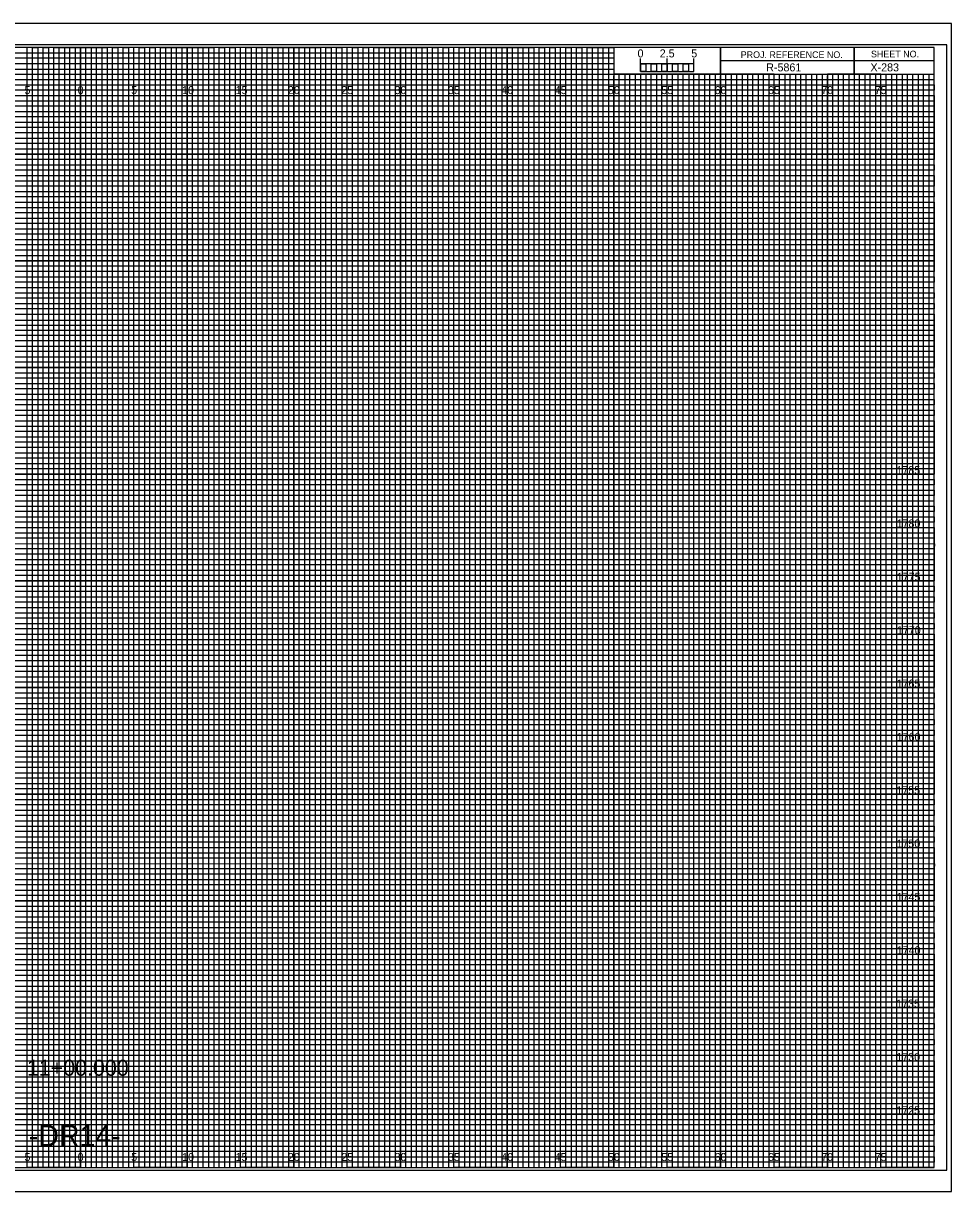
# Model space of a CAD drawing. Extents: x -7 to 162, y -2 to 437.
# Drawn here: x 74.6 to 161.7, y 107.7 to 217.2 of the extents above; entities that cross this region are included whole.
import ezdxf

# ---------------------------------------------------------------- set-up
doc = ezdxf.new("R2010")
doc.units = 0
for name, color, linetype in [('Prop Horizontal Alignment', 7, 'Continuous'), ('Prop XS Alignment Label', 7, 'Continuous'), ('Prop XS Bar Scale Labels', 7, 'Continuous'), ('Prop XS Project Number', 7, 'Continuous'), ('Prop XS Sheet Number', 7, 'Continuous'), ('Raster_Level_0', 7, 'Continuous'), ('Scratch_Level_3', 7, 'Continuous'), ('Sheet Cross Section CELL', 7, 'Continuous'), ('Sheet Cross Section Grid Major CELL', 7, 'Continuous'), ('Sheet Cross Section Grid Middle CELL', 7, 'Continuous'), ('Sheet Cross Section Grid Minor 1 CELL', 7, 'Continuous'), ('Sheet Cross Section Grid Minor 2 CELL', 7, 'Continuous'), ('Sheet Cross Section Scale CELL', 7, 'Continuous'), ('Sheet Cutting Line CELL', 7, 'Continuous'), ('Sheet DOT Grid CELL', 7, 'Continuous'), ('Sheet Plot Border Inside CELL', 7, 'Continuous'), ('Sheet Plot Border Outside CELL', 7, 'Continuous')]:
    doc.layers.add(name, color=color, linetype=linetype)

msp = doc.modelspace()

# ---------------------------------------------------------------- linework, layer by layer
at = {"layer": 'Sheet Cross Section CELL'}
for p, q in [((152.5, 215), (152.5, 212.5)), ((152.5, 212.5), (152.5, 215)), ((160, 213.75), (140, 213.75)), ((140, 213.75), (140, 212.5)), ((140, 212.5), (160, 212.5))]:
    msp.add_line(p, q, dxfattribs=at)
for points in [[(160, 215), (0, 215), (0, 110), (160, 110)], [(140, 215), (130, 215), (130, 212.52), (140, 212.52)], [(160, 215), (140, 215), (140, 212.5), (160, 212.5)]]:
    msp.add_lwpolyline(points, close=True, dxfattribs=at)
at = {"layer": 'Sheet Cross Section Grid Major CELL'}
for p, q in [((75, 215), (70, 215)), ((75, 110), (75, 215)), ((85, 215), (80, 215)), ((80, 215), (80, 110)), ((85, 110), (85, 215)), ((95, 215), (90, 215)), ((90, 215), (90, 110)), ((95, 110), (95, 215)), ((105, 215), (100, 215)), ((100, 215), (100, 110)), ((105, 110), (105, 215)), ((115, 215), (110, 215)), ((110, 215), (110, 110)), ((115, 110), (115, 215)), ((125, 215), (120, 215)), ((120, 215), (120, 110)), ((125, 110), (125, 215)), ((130, 215), (130, 110)), ((135, 110), (135, 212.5)), ((145, 212.5), (140, 212.5)), ((140, 212.5), (140, 110)), ((145, 110), (145, 212.5)), ((155, 212.5), (150, 212.5)), ((150, 212.5), (150, 110)), ((155, 110), (155, 212.5)), ((80, 110), (75, 110)), ((90, 110), (85, 110)), ((100, 110), (95, 110)), ((110, 110), (105, 110)), ((120, 110), (115, 110)), ((130, 110), (125, 110)), ((140, 110), (135, 110)), ((150, 110), (145, 110)), ((160, 110), (155, 110)), ((160, 110), (160, 110))]:
    msp.add_line(p, q, dxfattribs=at)
for points in [[(0, 210), (160, 210), (160, 205), (0, 205)], [(0, 200), (160, 200), (160, 195), (0, 195)], [(0, 190), (160, 190), (160, 185), (0, 185)], [(0, 180), (160, 180), (160, 175), (0, 175)], [(0, 170), (160, 170), (160, 165), (0, 165)], [(0, 160), (160, 160), (160, 155), (0, 155)], [(0, 150), (160, 150), (160, 145), (0, 145)], [(0, 140), (160, 140), (160, 135), (0, 135)], [(0, 130), (160, 130), (160, 125), (0, 125)], [(0, 120), (160, 120), (160, 115), (0, 115)]]:
    msp.add_lwpolyline(points, dxfattribs=at)
at = {"layer": 'Sheet Cross Section Grid Middle CELL'}
for points in [[(72.5, 110), (77.5, 110), (77.5, 215), (82.5, 215), (82.5, 110), (87.5, 110), (87.5, 215), (92.5, 215), (92.5, 110), (97.5, 110), (97.5, 215), (102.5, 215), (102.5, 110), (107.5, 110), (107.5, 215), (112.5, 215), (112.5, 110), (117.5, 110), (117.5, 215), (122.5, 215), (122.5, 110), (127.5, 110), (127.5, 215), (129.97, 215), (130, 215), (130, 212.5), (132.5, 212.5), (132.5, 110), (137.5, 110), (137.5, 212.5), (142.5, 212.5), (142.5, 110), (147.5, 110), (147.5, 212.5), (152.5, 212.5), (152.5, 110), (157.5, 110), (157.5, 212.5)], [(0, 212.5), (137.5, 212.5)], [(0, 202.5), (160, 202.5), (160, 207.5), (0, 207.5)], [(0, 192.5), (160, 192.5), (160, 197.5), (0, 197.5)], [(0, 182.5), (160, 182.5), (160, 187.5), (0, 187.5)], [(0, 172.5), (160, 172.5), (160, 177.5), (0, 177.5)], [(0, 162.5), (160, 162.5), (160, 167.5), (0, 167.5)], [(0, 152.5), (160, 152.5), (160, 157.5), (0, 157.5)], [(0, 142.5), (160, 142.5), (160, 147.5), (0, 147.5)], [(0, 132.5), (160, 132.5), (160, 137.5), (0, 137.5)], [(0, 122.5), (160, 122.5), (160, 127.5), (0, 127.5)], [(0, 112.5), (160, 112.5), (160, 117.5), (0, 117.5)]]:
    msp.add_lwpolyline(points, dxfattribs=at)
at = {"layer": 'Sheet Cross Section Grid Minor 1 CELL'}
for p, q in [((0, 214.5), (130, 214.5)), ((130, 213.99), (0, 213.99)), ((130, 214.5), (130, 213.99)), ((0, 213.5), (130, 213.5)), ((130, 212.94), (0, 212.94)), ((130, 213.5), (130, 212.94)), ((0, 212), (160, 212))]:
    msp.add_line(p, q, dxfattribs=at)
for points in [[(0, 211.5), (135, 211.5), (160, 211.5), (160, 211), (0, 211)], [(0, 210.5), (160, 210.5), (160, 209.5), (0, 209.5)], [(0, 209), (160, 209), (160, 208.5), (0, 208.49)], [(0, 208), (160, 208), (160, 207), (0, 207)], [(0, 206.5), (160, 206.5), (160, 206), (0, 206)], [(0, 205.5), (160, 205.5), (160, 204.5), (0, 204.5)], [(0, 204), (160, 204), (160, 203.5), (0, 203.5)], [(0, 203), (160, 203), (160, 202), (0, 202)], [(0, 201.5), (160, 201.5), (160, 201), (0, 201)], [(0, 200.5), (160, 200.5), (160, 199.5), (0, 199.5)], [(0, 199), (160, 199), (160, 198.5), (0, 198.5)], [(0, 198), (160, 198), (160, 196.97), (160, 196.5), (160, 196), (0, 196)], [(0, 197), (160, 197), (160, 196.5), (0, 196.5)], [(0, 195.5), (160, 195.5), (160, 194.5), (0, 194.52)], [(0, 194.52), (160, 194.5), (160, 194), (0, 194)], [(0, 193.5), (160, 193.5), (160, 193), (0, 193)], [(0, 192), (160, 192), (160, 191.5), (0, 191.5)], [(0, 191), (160, 191), (160, 190.5), (0, 190.5)], [(-0.04, 189.44), (160, 189.44), (160, 188.94), (-0.04, 188.94)], [(0, 188.5), (160, 188.5), (160, 188), (0, 188)], [(0, 187), (160, 187), (160, 186.5), (0, 186.5)], [(0, 186), (160, 186), (160, 185.5), (0, 185.5)], [(0, 184.5), (160, 184.5), (160, 184), (0, 184)], [(0, 183.5), (160, 183.5), (160, 183), (0, 183)], [(0, 182), (160, 182), (160, 181.5), (0, 181.5)], [(0, 181), (160, 181), (160, 180.5), (0, 180.5)], [(0, 179.5), (160, 179.5), (160, 178.99), (0, 179)], [(0, 178.5), (160, 178.5), (160, 178), (0, 178)], [(0, 177), (160, 177), (160, 176.5), (0, 176.5)], [(0, 176), (160, 176), (160, 175.5), (0, 175.5)], [(0, 174.5), (160, 174.5), (160, 174), (0, 174)], [(0, 173.5), (160, 173.5), (160, 173), (0, 173)], [(0, 172), (160, 172), (160, 171.5), (0, 171.5)], [(0, 171), (160, 171), (160, 170.5), (0, 170.5)], [(0, 169.5), (160, 169.5), (160, 169), (0, 169)], [(0, 168.5), (160.03, 168.46), (160, 168), (0, 168)], [(0, 167), (160, 167), (160, 166.5), (0, 166.5)], [(0, 166), (160, 166), (160, 165.5), (0, 165.5)], [(0, 164.5), (160, 164.5), (160, 164), (0, 164)], [(0, 163.5), (160, 163.5), (160, 163), (0, 163)], [(0, 162), (160, 162), (160, 161.5), (0, 161.5)], [(0, 161), (160, 161), (160, 160.5), (0, 160.5)], [(0, 159.5), (160, 159.5), (160, 159), (0, 159)], [(0, 158.5), (160, 158.5), (160, 158), (0, 158)], [(0, 157), (160, 157), (160, 156.5), (0, 156.5)], [(0, 156), (160, 156), (160, 155.5), (0, 155.5)], [(0, 154.5), (160, 154.5), (160, 154), (0, 154)], [(0, 153.5), (160, 153.5), (160, 153), (0, 153)], [(0, 152), (160, 152), (160, 151.5), (0, 151.5)], [(0, 151), (160, 151), (160, 150.5), (0, 150.5)], [(0, 149.5), (160, 149.5), (160, 148.99), (0, 149)], [(0, 148.5), (160, 148.5), (160, 148), (0, 148)], [(0, 147), (160, 147), (160, 146.5), (0, 146.5)], [(0, 146), (160, 146), (160, 145.5), (0, 145.5)], [(0, 144.5), (160, 144.5), (160, 144), (0, 144)], [(0, 143.5), (160, 143.5), (160, 143), (0, 143)], [(0, 142), (160, 142), (160, 141.5), (0, 141.5)], [(0, 141), (160, 141), (160, 140.5), (0, 140.5)], [(0, 139.5), (160, 139.5), (160, 139), (0, 139)], [(0, 138.5), (160.03, 138.46), (160, 138), (0, 138)], [(0, 137), (160, 137), (160, 136.5), (0, 136.5)], [(0, 136), (160, 136), (160, 135.5), (0, 135.5)], [(0, 134.5), (160, 134.5), (160, 134), (0, 134)], [(0, 133.5), (160, 133.5), (160, 133), (0, 133)], [(0, 132), (160, 132), (160, 131.5), (0, 131.5)], [(0, 131), (160, 131), (160, 130.5), (0, 130.5)], [(0, 129.5), (160, 129.5), (160, 129), (0, 129)], [(0, 128.5), (160, 128.5), (160, 128), (0, 128)], [(0, 127), (160, 127), (160, 126.5), (0, 126.5)], [(0, 126), (160, 126), (160, 125.5), (0, 125.5)], [(0, 124.5), (160, 124.5), (160, 124), (0, 124)], [(0, 123.5), (160, 123.5), (160, 123), (0, 123)], [(0, 122), (160, 122), (160, 121.5), (0, 121.5)], [(0, 121), (160, 121), (160, 120.5), (0, 120.5)], [(0, 119.5), (160, 119.5), (160, 119), (0, 119)], [(0, 118.5), (160, 118.5), (160, 118), (0, 118)], [(0, 117), (160, 117), (160, 116.5), (0, 116.5)], [(0, 116), (160, 116), (160, 115.5), (0, 115.5)], [(0, 114.5), (160, 114.5), (160, 114), (0, 114)], [(0, 113.5), (160, 113.5), (160, 113), (0, 113)], [(0, 112), (160, 112), (160, 111.5), (0, 111.5)], [(0, 111), (160, 111), (160, 110.5), (0, 110.5)]]:
    msp.add_lwpolyline(points, dxfattribs=at)
at = {"layer": 'Sheet Cross Section Grid Minor 2 CELL'}
for p, q in [((133.5, 212.5), (133, 212.5)), ((133, 212.5), (133, 110)), ((133.5, 110), (133.5, 212.5)), ((134.5, 212.5), (134, 212.5)), ((134, 212.5), (134, 110)), ((134.5, 110), (134.5, 212.5)), ((133, 110), (132.5, 110)), ((134, 110), (133.5, 110))]:
    msp.add_line(p, q, dxfattribs=at)
for points in [[(75, 110), (75.5, 110), (75.5, 215), (76, 215), (76, 110)], [(76, 110), (76.5, 110), (76.5, 215), (77, 215), (77, 110)], [(77.5, 110), (78, 110), (78, 215), (78.5, 215), (78.5, 110)], [(78.5, 110), (79, 110), (79, 215), (79.5, 215), (79.5, 110)], [(80, 110), (80.5, 110), (80.5, 215), (81, 215), (81, 110)], [(81, 110), (81.5, 110), (81.5, 215), (82, 215), (82, 110)], [(82.5, 110), (83, 110), (83, 215), (83.5, 215), (83.5, 110)], [(83.5, 110), (84, 110), (84, 215), (84.5, 215), (84.5, 110)], [(85, 110), (85.5, 110), (85.5, 215), (86, 215), (86, 110)], [(86, 110), (86.5, 110), (86.5, 215), (87, 215), (87, 110)], [(87.5, 110), (88, 110), (88, 215), (88.5, 215), (88.5, 110)], [(88.5, 110), (89, 110), (89, 215), (89.5, 215), (89.5, 110)], [(90, 110), (90.5, 110), (90.5, 215), (91, 215), (91, 110)], [(91, 110), (91.5, 110), (91.5, 215), (92, 215), (92, 110)], [(92.5, 110), (93, 110), (93, 215), (93.5, 215), (93.5, 110)], [(93.5, 110), (94, 110), (94, 215), (94.5, 215), (94.5, 110)], [(95, 110), (95.5, 110), (95.5, 215), (96, 215), (96, 110)], [(96, 110), (96.5, 110), (96.5, 215), (97, 215), (97, 110)], [(97.5, 110), (98, 110), (98, 215), (98.5, 215), (98.5, 110)], [(98.5, 110), (99, 110), (99, 215), (99.5, 215), (99.5, 110)], [(100, 110), (100.5, 110), (100.5, 215), (101, 215), (101, 110)], [(101, 110), (101.5, 110), (101.5, 215), (102, 215), (102, 110)], [(102.5, 110), (103, 110), (103, 215), (103.5, 215), (103.5, 110)], [(103.5, 110), (104, 110), (104, 215), (104.5, 215), (104.5, 110)], [(105, 110), (105.5, 110), (105.5, 215), (106, 215), (106, 110)], [(106, 110), (106.5, 110), (106.5, 215), (107, 215), (107, 110)], [(107.5, 110), (108, 110), (108, 215), (108.5, 215), (108.5, 110)], [(108.5, 110), (109, 110), (109, 215), (109.5, 215), (109.5, 110)], [(110, 110), (110.5, 110), (110.5, 215), (111, 215), (111, 110)], [(111, 110), (111.5, 110), (111.5, 215), (112, 215), (112, 110)], [(112.5, 110), (113, 110), (113, 215), (113.5, 215), (113.5, 110)], [(113.5, 110), (114, 110), (114, 215), (114.5, 215), (114.5, 110)], [(115, 110), (115.5, 110), (115.5, 215), (116, 215), (116, 110)], [(116, 110), (116.5, 110), (116.5, 215), (117, 215), (117, 110)], [(117.5, 110), (118, 110), (118, 215), (118.5, 215), (118.5, 110)], [(118.5, 110), (119, 110), (119, 215), (119.5, 215), (119.5, 110)], [(120, 110), (120.5, 110), (120.5, 215), (121, 215), (121, 110)], [(121, 110), (121.5, 110), (121.5, 215), (122, 215), (122, 110)], [(122.5, 110), (123, 110), (123, 215), (123.5, 215), (123.5, 110)], [(123.5, 110), (124, 110), (124, 215), (124.5, 215), (124.5, 110)], [(125, 110), (125.5, 110), (125.5, 215), (126, 215), (126, 110)], [(126, 110), (126.5, 110), (126.5, 215), (127, 215), (127, 110)], [(127.5, 110), (128, 110), (128, 215), (128.5, 215), (128.5, 110)], [(128.5, 110), (129, 110), (129, 215), (129.5, 215), (129.5, 110)], [(130, 110), (130.5, 110), (130.5, 212.5), (131.01, 212.5), (131.01, 110)], [(131, 110), (131.5, 110), (131.5, 212.5), (132, 212.5), (132, 110)], [(135, 110), (135.49, 110), (135.49, 212.5), (136, 212.5), (136, 110)], [(136, 110), (136.5, 110), (136.5, 212.5), (137.03, 212.5), (137.03, 110)], [(137.5, 110), (138, 110), (138, 212.5), (138.5, 212.5), (138.5, 110)], [(138.5, 110), (139, 110), (139, 212.5), (139.5, 212.5), (139.5, 110)], [(140, 110), (140.5, 110), (140.5, 212.5), (141, 212.5), (141, 110)], [(141, 110), (141.5, 110), (141.5, 212.5), (142, 212.5), (142, 110)], [(142.5, 110), (143, 110), (143, 212.5), (143.5, 212.5), (143.5, 110)], [(143.5, 110), (144, 110), (144, 212.5), (144.5, 212.5), (144.5, 110)], [(145, 110), (145.5, 110), (145.5, 212.5), (146, 212.5), (146, 110)], [(146, 110), (146.5, 110), (146.5, 212.5), (147, 212.5), (147, 110)], [(147.5, 110), (148, 110), (148, 212.5), (148.5, 212.5), (148.5, 110)], [(148.5, 110), (149, 110), (149, 212.5), (149.5, 212.5), (149.5, 110)], [(150, 110), (150.5, 110), (150.5, 212.5), (151, 212.5), (151, 110)], [(151, 110), (151.5, 110), (151.5, 212.5), (152, 212.5), (152, 110)], [(152.5, 110), (153, 110), (153, 212.5), (153.5, 212.5), (153.5, 110)], [(153.5, 110), (154, 110), (154, 212.5), (154.5, 212.5), (154.5, 110)], [(155, 110), (155.5, 110), (155.5, 212.5), (156, 212.5), (156, 110)], [(156, 110), (156.5, 110), (156.5, 212.5), (157, 212.5), (157, 110)], [(157.5, 110), (158, 110), (158, 212.5), (158.5, 212.5), (158.5, 110)], [(158.5, 110), (159, 110), (159, 212.5), (159.5, 212.5), (159.5, 110)]]:
    msp.add_lwpolyline(points, dxfattribs=at)
at = {"layer": 'Sheet Cross Section Scale CELL'}
for p, q in [((132.5, 212.75), (132.5, 213.95)), ((132.5, 213.45), (132.5, 213.95)), ((135, 212.75), (135, 213.95)), ((137.5, 212.75), (137.5, 213.95)), ((137.5, 213.45), (137.5, 213.95))]:
    msp.add_line(p, q, dxfattribs=at)
for points in [[(137.5, 213.45), (132.5, 213.45), (132.5, 212.75), (137.5, 212.75)], [(132.5, 213.45), (133, 213.45), (133, 212.75), (132.5, 212.75)], [(133.5, 213.45), (134, 213.45), (134, 212.75), (133.5, 212.75)], [(134.5, 213.45), (135, 213.45), (135, 212.75), (134.5, 212.75)], [(135.5, 213.45), (136, 213.45), (136, 212.75), (135.5, 212.75)], [(136.5, 213.45), (137, 213.45), (137, 212.75), (136.5, 212.75)]]:
    msp.add_lwpolyline(points, close=True, dxfattribs=at)
at = {"layer": 'Sheet Cutting Line CELL'}
for p, q in [((161.65, 217.25), (-6.7, 217.25)), ((-6.7, 107.75), (161.65, 107.75))]:
    msp.add_line(p, q, dxfattribs=at)
at = {"layer": 'Sheet DOT Grid CELL'}
for p, q in [((75, 110), (75, 215)), ((80, 110), (80, 215)), ((85, 110), (85, 215)), ((90, 110), (90, 215)), ((95, 110), (95, 215)), ((100, 110), (100, 215)), ((105, 110), (105, 215)), ((110, 110), (110, 215)), ((115, 110), (115, 215)), ((120, 110), (120, 215)), ((125, 110), (125, 215)), ((130, 110), (130, 212.34)), ((135, 110), (135, 212.34)), ((140, 110), (140, 212.34)), ((145, 110), (145, 212.34)), ((150, 110), (150, 212.34)), ((155, 110), (155, 212.34)), ((0, 210), (160, 210)), ((0, 205), (160, 205)), ((0, 200), (160, 200)), ((0, 195), (160, 195)), ((0, 190), (160, 190)), ((0, 185), (160, 185)), ((0, 180), (160, 180)), ((0, 175), (160, 175)), ((0, 170), (160, 170)), ((0, 165), (160, 165)), ((0, 160), (160, 160)), ((0, 155), (160, 155)), ((0, 150), (160, 150)), ((0, 145), (160, 145)), ((0, 140), (160, 140)), ((0, 135), (160, 135)), ((0, 130), (160, 130)), ((0, 125), (160, 125)), ((0, 120), (160, 120)), ((0, 115), (160, 115))]:
    msp.add_line(p, q, dxfattribs=at)
at = {"layer": 'Sheet Plot Border Inside CELL'}
msp.add_lwpolyline([(-5.4, 109.75), (161.2, 109.75), (161.2, 215.25), (-5.4, 215.25)], close=True, dxfattribs=at)
at = {"layer": 'Sheet Plot Border Outside CELL'}
msp.add_lwpolyline([(-6.7, 107.75), (161.65, 107.75), (161.65, 217.25), (-6.7, 217.25)], close=True, dxfattribs=at)

# ---------------------------------------------------------------- texts
at = {"layer": 'Prop Horizontal Alignment'}
msp.add_text('11+00.000', height=1.5, dxfattribs=at).set_placement((74.97, 118.61))
at = {"layer": 'Prop XS Alignment Label'}
msp.add_text('-DR14-', height=2, dxfattribs=at).set_placement((75.15, 112))
at = {"layer": 'Prop XS Bar Scale Labels'}
for s, p in [('2.5', (134.29, 214.06)), ('5', (137.24, 214.06))]:
    msp.add_text(s, height=0.75, dxfattribs=at).set_placement(p)
at = {"layer": 'Prop XS Project Number'}
msp.add_text('R-5861', height=0.75, dxfattribs=at).set_placement((144.27, 212.75))
at = {"layer": 'Prop XS Sheet Number'}
msp.add_text('X-283', height=0.75, dxfattribs=at).set_placement((154.04, 212.75))
at = {"layer": 'Raster_Level_0'}
for s, p in [('5', (74.74, 210.62)), ('0', (79.73, 210.62)), ('0', (79.73, 210.62)), ('5', (84.74, 210.62)), ('10', (89.52, 210.62)), ('15', (94.53, 210.62)), ('20', (99.43, 210.62)), ('25', (104.44, 210.62)), ('30', (109.43, 210.62)), ('35', (114.44, 210.62)), ('40', (119.43, 210.62)), ('45', (124.44, 210.62)), ('50', (129.43, 210.62)), ('55', (134.44, 210.62)), ('60', (139.43, 210.62)), ('65', (144.44, 210.62)), ('70', (149.43, 210.62)), ('75', (154.44, 210.62)), ('5', (74.74, 110.62)), ('0', (79.73, 110.62)), ('0', (79.73, 110.62)), ('5', (84.74, 110.62)), ('10', (89.52, 110.62)), ('15', (94.53, 110.62)), ('20', (99.43, 110.62)), ('25', (104.44, 110.62)), ('30', (109.43, 110.62)), ('35', (114.44, 110.62)), ('40', (119.43, 110.62)), ('45', (124.44, 110.62)), ('50', (129.43, 110.62)), ('55', (134.44, 110.62)), ('60', (139.43, 110.62)), ('65', (144.44, 110.62)), ('70', (149.43, 110.62)), ('75', (154.44, 110.62))]:
    msp.add_text(s, height=0.75, dxfattribs=at).set_placement(p)
at = {"layer": 'Scratch_Level_3'}
for s, p in [('1785', (156.48, 175)), ('1780', (156.49, 170)), ('1775', (156.51, 165)), ('1770', (156.52, 160)), ('1765', (156.49, 155)), ('1760', (156.5, 150)), ('1755', (156.47, 145)), ('1750', (156.48, 140)), ('1745', (156.49, 135)), ('1740', (156.5, 130)), ('1735', (156.45, 125)), ('1730', (156.46, 120)), ('1725', (156.46, 115))]:
    msp.add_text(s, height=0.75, dxfattribs=at).set_placement(p)
at = {"layer": 'Sheet Cross Section CELL'}
for s, p in [('PROJ. REFERENCE NO.', (141.88, 214)), ('SHEET NO.', (154.09, 214.06))]:
    msp.add_text(s, height=0.625, dxfattribs=at).set_placement(p)
at = {"layer": 'Sheet Cross Section Scale CELL'}
msp.add_text('0', height=0.75, dxfattribs=at).set_placement((132.21, 214.06))

doc.saveas('drawing.dxf')
